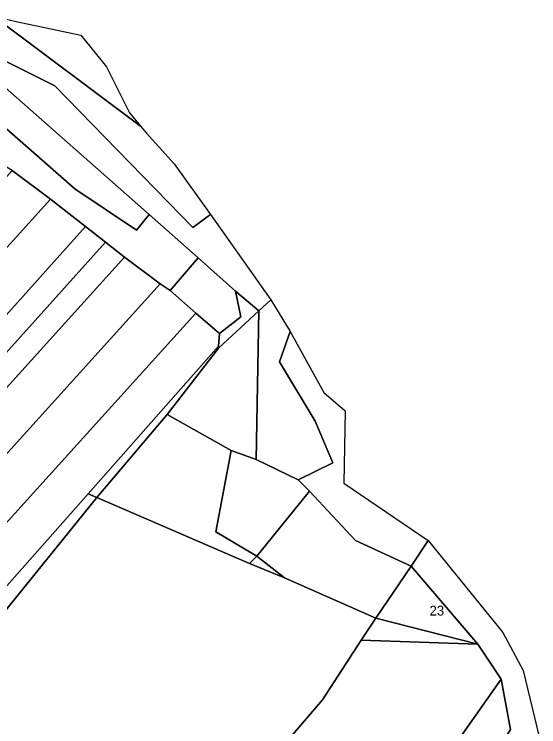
# Model space of a CAD drawing. Extents: x -521261 to -517465, y -1182764 to -1179456.
# Drawn here: x -518914.6 to -518647.5, y -1180409.7 to -1180047.1 of the extents above; entities that cross this region are included whole.
import ezdxf

# ---------------------------------------------------------------- set-up
doc = ezdxf.new("R2010")
doc.units = 0
for name, color, linetype in [('95560013', 7, 'Continuous'), ('95610013', 7, 'Continuous'), ('95620013', 7, 'Continuous'), ('95640013', 7, 'Continuous'), ('95660013', 7, 'Continuous')]:
    doc.layers.add(name, color=color, linetype=linetype)

msp = doc.modelspace()

# ---------------------------------------------------------------- linework, layer by layer
at = {"layer": '95560013'}
for points in [[(-518919.21, -1180084.38), (-518845.86, -1180148.96), (-518852.28, -1180156.99), (-518883.79, -1180135.9), (-518935.36, -1180090.75), (-518926.21, -1180077.8)], [(-518896.17, -1180141.1), (-519010.01, -1180267.06), (-519015.36, -1180262.2), (-519027.48, -1180251.97), (-518915.64, -1180126.65)], [(-518878.35, -1180155.06), (-518992.47, -1180282.53), (-518995.08, -1180280.28), (-519010.01, -1180267.06), (-518896.17, -1180141.1)], [(-518868.14, -1180162.99), (-518983.19, -1180290.9), (-518992.47, -1180282.53), (-518878.35, -1180155.06)], [(-518858.5, -1180170.71), (-518974.28, -1180298.61), (-518975.76, -1180297.28), (-518983.19, -1180290.9), (-518868.14, -1180162.99)], [(-518840.33, -1180184.24), (-518957.32, -1180313.77), (-518974.28, -1180298.61), (-518858.5, -1180170.71)], [(-518835.28, -1180187.7), (-518822.15, -1180199.1), (-518939.93, -1180329.25), (-518957.32, -1180313.77), (-518840.33, -1180184.24)], [(-518810.04, -1180209.46), (-518810.54, -1180215.99), (-518876.88, -1180291.05), (-518923.7, -1180343.73), (-518939.93, -1180329.25), (-518822.15, -1180199.1)], [(-518810.64, -1180217), (-518836.78, -1180250.69), (-518872.62, -1180293.06), (-518876.88, -1180291.05), (-518810.54, -1180215.99)], [(-518804.19, -1180268.99), (-518811.96, -1180310.49), (-518791.03, -1180322.79), (-518794.77, -1180326.6), (-518872.62, -1180293.06), (-518836.78, -1180250.69)], [(-518791.47, -1180273.65), (-518769.97, -1180283.94), (-518764.31, -1180289.83), (-518791.03, -1180322.79), (-518811.96, -1180310.49), (-518804.19, -1180268.99)], [(-518872.62, -1180293.06), (-518924.13, -1180356.64), (-518966.24, -1180412.4), (-518988.53, -1180447.41), (-519008.28, -1180481.84), (-519035.64, -1180467.78), (-518923.7, -1180343.73), (-518876.88, -1180291.05)], [(-518737.91, -1180365.66), (-518730.54, -1180354.36), (-518678.54, -1180367.65)], [(-518678.54, -1180367.65), (-518666.6, -1180385.39), (-518689.17, -1180417.51), (-518675.05, -1180432.18), (-518735.07, -1180483.69), (-518805.34, -1180547.49), (-518819.9, -1180562.16), (-518832.97, -1180577.12), (-518849.54, -1180575.21), (-518844.2, -1180566.48), (-518879.8, -1180531.46), (-518795.16, -1180439.81), (-518757.62, -1180395.93), (-518737.91, -1180365.66)]]:
    msp.add_lwpolyline(points, close=True, dxfattribs=at)
msp.add_lwpolyline([(-518924.13, -1180356.64), (-518872.62, -1180293.06), (-518794.77, -1180326.6), (-518776.93, -1180333.89), (-518730.54, -1180354.36), (-518737.91, -1180365.66), (-518757.62, -1180395.93), (-518795.16, -1180439.81), (-518879.8, -1180531.46), (-518887.35, -1180523.29), (-518912.15, -1180557.37), (-518933.81, -1180591.04)], dxfattribs=at)
at = {"layer": '95610013'}
for points in [[(-518930.62, -1180047.06), (-518925.25, -1180048.07), (-518850.28, -1180104.06), (-518847.22, -1180107.51), (-518833.18, -1180123.22), (-518814.68, -1180148.98), (-518823.68, -1180155.62), (-518894, -1180083.54), (-518921.09, -1180070), (-518950.88, -1180054.57)], [(-518913.62, -1180050.8), (-518880.77, -1180057.74), (-518867.6, -1180073.76), (-518855.92, -1180097.31), (-518850.28, -1180104.06), (-518925.25, -1180048.07)], [(-518935.36, -1180090.75), (-518883.79, -1180135.9), (-518852.28, -1180156.99), (-518845.86, -1180148.96), (-518820.97, -1180171.01), (-518835.28, -1180187.7), (-518840.33, -1180184.24), (-518858.5, -1180170.71), (-518868.14, -1180162.99), (-518878.35, -1180155.06), (-518896.17, -1180141.1), (-518915.64, -1180126.65), (-518929.07, -1180118.68), (-518935.28, -1180111.55), (-518942.93, -1180095.78), (-518937.67, -1180092.99)], [(-518820.97, -1180171.01), (-518801.96, -1180187.97), (-518799.18, -1180200.97), (-518810.04, -1180209.46), (-518822.15, -1180199.1), (-518835.28, -1180187.7)], [(-518790.12, -1180198.06), (-518791.47, -1180273.65), (-518804.19, -1180268.99), (-518836.78, -1180250.69), (-518810.64, -1180217)], [(-518661.93, -1180411.14), (-518675.05, -1180432.18), (-518689.17, -1180417.51), (-518666.6, -1180385.39)]]:
    msp.add_lwpolyline(points, close=True, dxfattribs=at)
at = {"layer": '95620013'}
for points in [[(-518790.12, -1180198.06), (-518784, -1180192.42), (-518774.14, -1180208.57), (-518779.54, -1180224.01), (-518761.37, -1180254.15), (-518752.41, -1180275.27), (-518769.97, -1180283.94), (-518791.47, -1180273.65)], [(-518779.54, -1180224.01), (-518774.14, -1180208.57), (-518756.96, -1180239.5), (-518746.13, -1180248.91), (-518746.71, -1180285.66), (-518703.81, -1180314.81), (-518712.53, -1180327.88), (-518740.76, -1180314.9), (-518764.31, -1180289.83), (-518769.97, -1180283.94), (-518752.41, -1180275.27), (-518761.37, -1180254.15)], [(-518740.76, -1180314.9), (-518712.53, -1180327.88), (-518730.54, -1180354.36), (-518776.93, -1180333.89), (-518791.03, -1180322.79), (-518764.31, -1180289.83)], [(-518712.53, -1180327.88), (-518703.81, -1180314.81), (-518665.78, -1180361.68), (-518655.44, -1180381.08), (-518647.53, -1180414.17), (-518675.05, -1180432.18), (-518661.93, -1180411.14), (-518666.6, -1180385.39), (-518678.54, -1180367.65)], [(-518794.77, -1180326.6), (-518791.03, -1180322.79), (-518776.93, -1180333.89)], [(-518730.54, -1180354.36), (-518712.53, -1180327.88), (-518678.54, -1180367.65)]]:
    msp.add_lwpolyline(points, close=True, dxfattribs=at)
at = {"layer": '95640013'}
for points in [[(-518952.1, -1180054.93), (-518950.88, -1180054.57), (-518921.09, -1180070), (-518894, -1180083.54), (-518823.68, -1180155.62), (-518814.68, -1180148.98), (-518784, -1180192.42), (-518790.12, -1180198.06), (-518801.96, -1180187.97), (-518820.97, -1180171.01), (-518845.86, -1180148.96), (-518919.21, -1180084.38), (-518926.21, -1180077.8)], [(-518801.96, -1180187.97), (-518790.12, -1180198.06), (-518810.64, -1180217), (-518810.54, -1180215.99), (-518810.04, -1180209.46), (-518799.18, -1180200.97)]]:
    msp.add_lwpolyline(points, close=True, dxfattribs=at)
at = {"layer": '95660013'}
for points in [[(-518925.25, -1180048.07), (-518913.62, -1180050.8), (-518880.77, -1180057.74), (-518867.6, -1180073.76), (-518855.92, -1180097.31), (-518850.28, -1180104.06), (-518847.22, -1180107.51), (-518833.18, -1180123.22), (-518814.68, -1180148.98), (-518784, -1180192.42), (-518790.12, -1180198.06), (-518791.47, -1180273.65), (-518769.97, -1180283.94), (-518764.31, -1180289.83), (-518791.03, -1180322.79), (-518794.77, -1180326.6), (-518776.93, -1180333.89), (-518730.54, -1180354.36), (-518678.54, -1180367.65), (-518666.6, -1180385.39), (-518661.93, -1180411.14)], [(-518661.93, -1180411.14), (-518666.6, -1180385.39), (-518678.54, -1180367.65), (-518730.54, -1180354.36), (-518776.93, -1180333.89), (-518794.77, -1180326.6), (-518791.03, -1180322.79), (-518764.31, -1180289.83), (-518769.97, -1180283.94), (-518791.47, -1180273.65), (-518790.12, -1180198.06), (-518784, -1180192.42), (-518774.14, -1180208.57), (-518756.96, -1180239.5), (-518746.13, -1180248.91), (-518746.71, -1180285.66), (-518703.81, -1180314.81), (-518665.78, -1180361.68), (-518655.44, -1180381.08), (-518647.53, -1180414.17)]]:
    msp.add_lwpolyline(points, dxfattribs=at)

# ---------------------------------------------------------------- texts
msp.add_text('23', height=5, rotation=0, dxfattribs=at).set_placement((-518703.14, -1180353.06))

doc.saveas('drawing.dxf')
